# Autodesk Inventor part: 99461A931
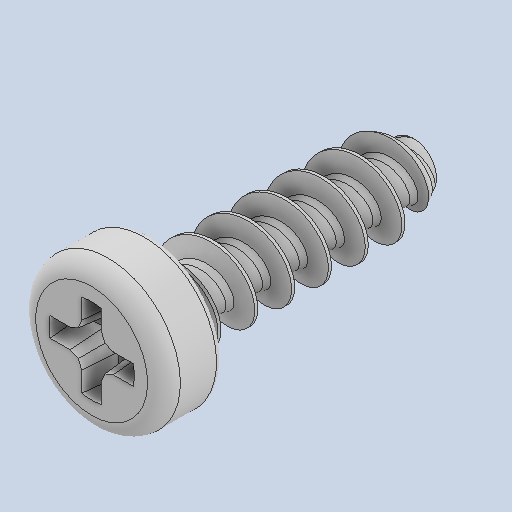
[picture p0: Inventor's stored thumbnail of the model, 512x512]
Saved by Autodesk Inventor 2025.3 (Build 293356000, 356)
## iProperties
Company: McMaster Carr Supply
Created: 2026-06
Part Number: 99461A931
Material: Genérico
Description: Tornillo formador de rosca para plástico M2.5 × 8 mm
Document SubType Name: Modeling
Designer: Luis MuÃ±oz
Density: 1 g/cm^3
Appearance: Valor por defecto
Project: TESIS 2 - Plataforma mecatrÃ³nica preventiva desacoplada
Vendor: McMaster-Carr
Sending System: SolidWorks 2024
Preprocessor: SwSTEP 2.0
Title: Tornillo formador de rosca para plÃ¡stico M2.5 Ã— 8 mm
Author: McMaster Carr Supply
Revision Number: 00
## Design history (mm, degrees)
feature "Boss-Extrude4"
node "Sólido1"
